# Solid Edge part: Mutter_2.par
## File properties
Sűrűség: 0,000 kg/m^3
Pontosság: 0,990
Author: ahadarics
Last saved by: ahadarics
Revision: 77
Username: ahadarics
Dokumentum tartalom típus: 0
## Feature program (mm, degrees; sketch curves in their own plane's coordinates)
base feature "unnamed BaseFeature 1"
thread "unnamed Thread 1"
chamfer "unnamed Chamfer 1"
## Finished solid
Body 1: solid body, 13 faces, 24 edges, 12 vertices.
  Faces by surface: plane 8, cone 4, cylinder 1
  Edges by curve: spline 12, circle 6, line 6
Bounding box of the edges (mm): 31.177 x 27.000 x 8.000, from (-15.5885, -13.5, -4) to (15.5885, 13.5, 4).
Cylindrical faces by radius (mm): R10.188 x1
Conical faces (half-angle, radius in mm at the cone's reference point): 45 deg R10.188 x1, 45 deg R11.188 x1, 75 deg R14.5 x2
Planar faces by outward normal: +y 1, +z 1, -y 1, -z 1, oblique 4
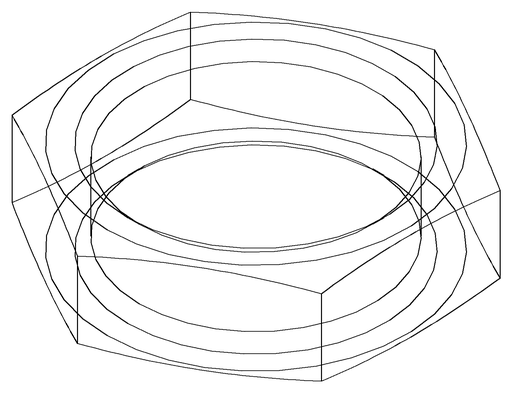
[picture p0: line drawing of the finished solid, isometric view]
